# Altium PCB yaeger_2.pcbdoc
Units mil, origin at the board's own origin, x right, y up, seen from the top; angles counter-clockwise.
Board outline 3420.5 x 4365.1 mil, 2 copper layers (Top Layer, Bottom Layer), stack 62.2 mil thick; 11 components, 23 nets, 142 pads, 5 vias.
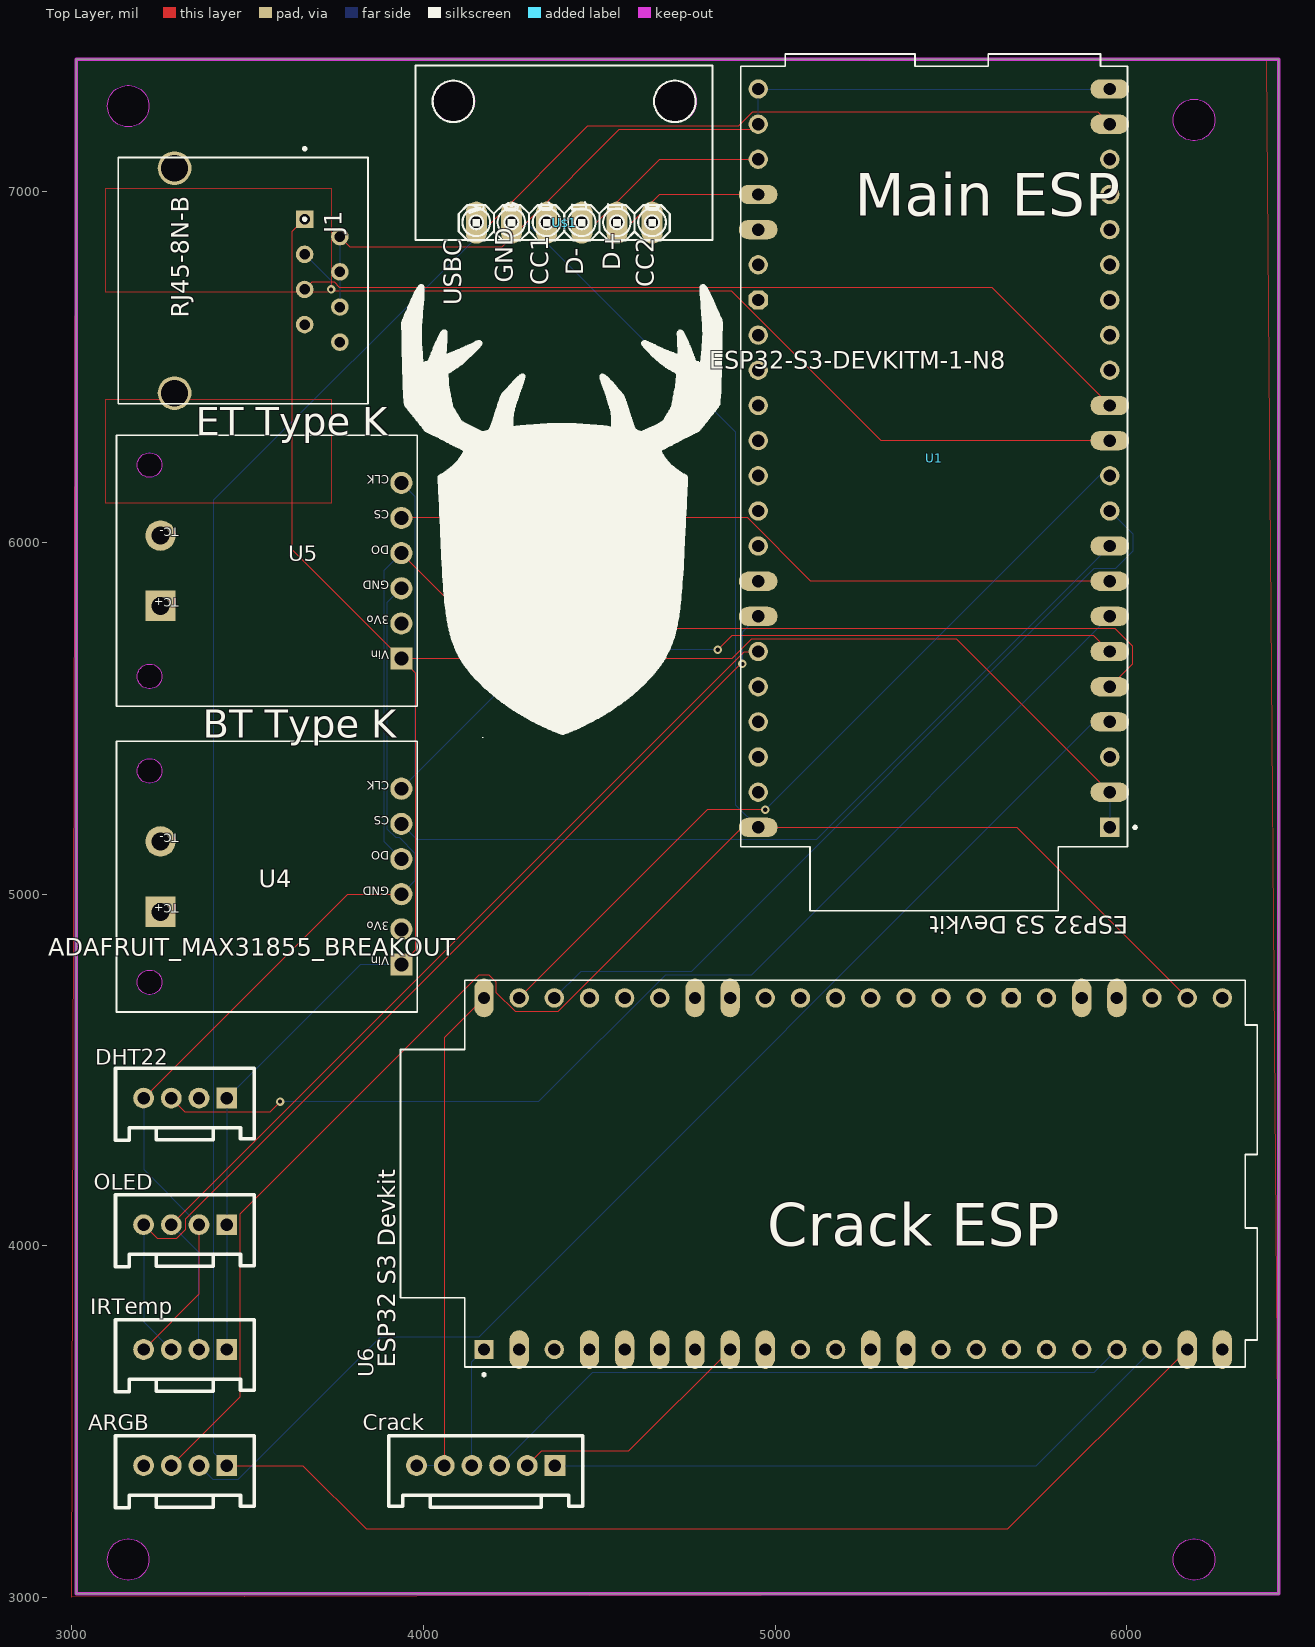
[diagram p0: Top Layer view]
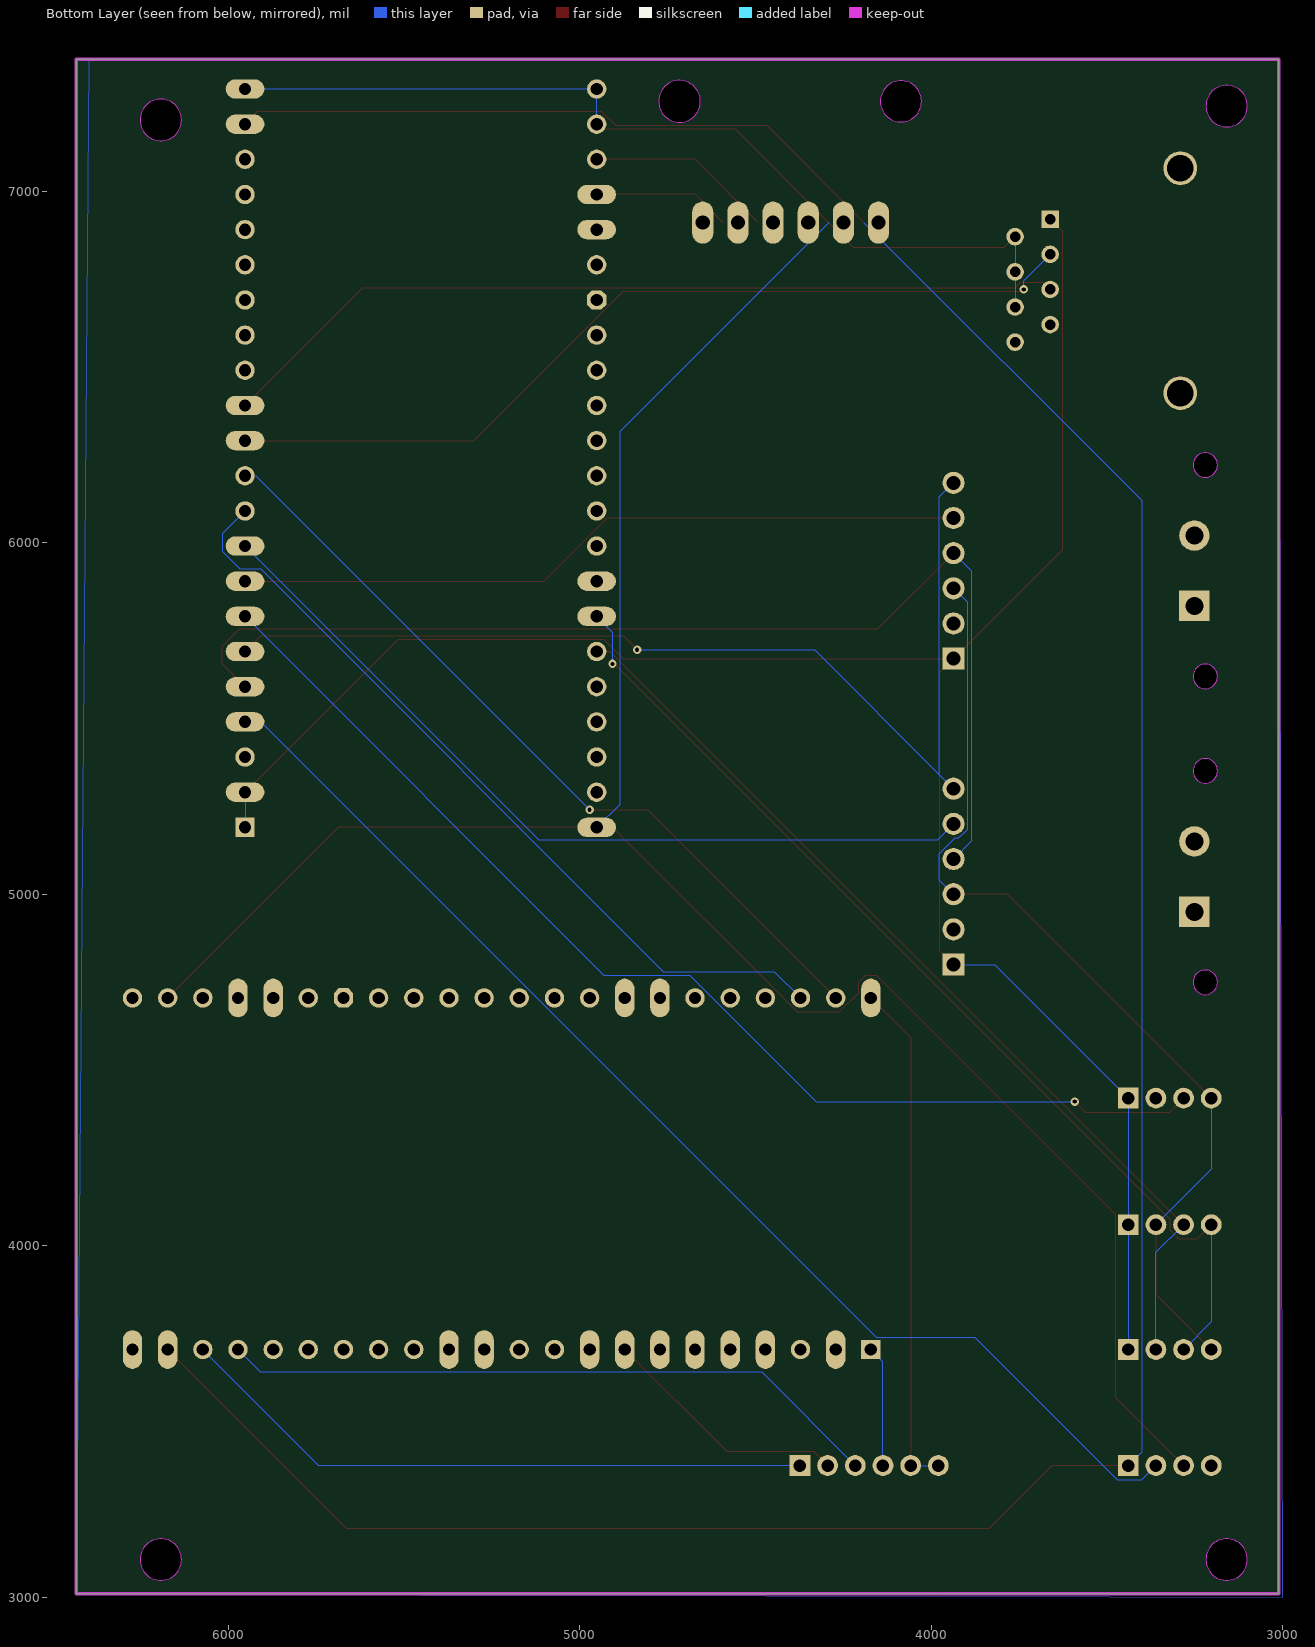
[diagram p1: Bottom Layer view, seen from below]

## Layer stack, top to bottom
Top Solder Mask Layer: solder mask 0.4, Dk 3.3
Top Layer: signal copper 1.4
Dielectric1: surface 59.4, FR4, Dk 4.5
Bottom Layer: signal copper 1.4
Bottom Solder Mask Layer: solder mask 0.4, Dk 3.3

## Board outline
3011.8,7375.1 3011.8,3010 6432.3,3010 6432.3,7375.1
cut-out: 4145.1,7255 4144.7,7248.2 4143.5,7241.5 4141.5,7234.9 4138.8,7228.7 4135.4,7222.8 4131.3,7217.3 4126.7,7212.3 4121.4,7208 4115.7,7204.2 4109.6,7201.1 4103.2,7198.8 4096.6,7197.2 4089.8,7196.4 4083,7196.4 4076.2,7197.2 4069.6,7198.8 4063.2,7201.1 4057.1,7204.2 4051.4,7208 4046.1,7212.3 4041.5,7217.3 4037.4,7222.8 4034,7228.7 4031.3,7234.9 4029.3,7241.5 4028.1,7248.2 4027.7,7255 4028.1,7261.8 4029.3,7268.5 4031.3,7275.1 4034,7281.3 4037.4,7287.3 4041.5,7292.7 4046.1,7297.7 4051.4,7302.1 4057.1,7305.8 4063.2,7308.9 4069.6,7311.2 4076.2,7312.8 4083,7313.6 4089.8,7313.6 4096.6,7312.8 4103.2,7311.2 4109.6,7308.9 4115.7,7305.8 4121.4,7302.1 4126.7,7297.7 4131.3,7292.7 4135.4,7287.3 4138.8,7281.3 4141.5,7275.1 4143.5,7268.5 4144.7,7261.8
cut-out: 4775.9,7255 4775.5,7248.2 4774.4,7241.5 4772.5,7235 4769.8,7228.7 4766.5,7222.8 4762.5,7217.3 4757.9,7212.3 4752.7,7207.8 4747.1,7204 4741.1,7200.8 4734.7,7198.3 4728.2,7196.6 4721.4,7195.6 4714.6,7195.4 4707.8,7196 4701.2,7197.4 4694.7,7199.5 4688.5,7202.3 4682.7,7205.8 4677.3,7210 4672.4,7214.7 4668.1,7220 4664.4,7225.7 4661.4,7231.8 4659.1,7238.2 4657.6,7244.9 4656.8,7251.6 4656.8,7258.4 4657.6,7265.2 4659.1,7271.8 4661.4,7278.2 4664.4,7284.3 4668.1,7290 4672.4,7295.3 4677.3,7300.1 4682.7,7304.2 4688.5,7307.7 4694.7,7310.6 4701.2,7312.7 4707.8,7314 4714.6,7314.6 4721.4,7314.4 4728.2,7313.4 4734.7,7311.7 4741.1,7309.2 4747.1,7306.1 4752.7,7302.2 4757.9,7297.8 4762.5,7292.7 4766.5,7287.2 4769.8,7281.3 4772.5,7275 4774.4,7268.5 4775.5,7261.8
cut-out: 3219,7241.5 3218.6,7234.7 3217.4,7227.9 3215.4,7221.3 3212.7,7215 3209.3,7209.1 3205.2,7203.6 3200.5,7198.6 3195.2,7194.1 3189.5,7190.4 3183.3,7187.3 3176.9,7184.9 3170.2,7183.4 3163.4,7182.6 3156.5,7182.6 3149.7,7183.4 3143,7184.9 3136.6,7187.3 3130.4,7190.4 3124.7,7194.1 3119.4,7198.6 3114.7,7203.6 3110.6,7209.1 3107.2,7215 3104.4,7221.3 3102.5,7227.9 3101.3,7234.7 3100.9,7241.5 3101.3,7248.4 3102.5,7255.1 3104.4,7261.7 3107.2,7268 3110.6,7274 3114.7,7279.5 3119.4,7284.5 3124.7,7288.9 3130.4,7292.7 3136.6,7295.7 3143,7298.1 3149.7,7299.7 3156.5,7300.5 3163.4,7300.5 3170.2,7299.7 3176.9,7298.1 3183.3,7295.7 3189.5,7292.7 3195.2,7288.9 3200.5,7284.5 3205.2,7279.5 3209.3,7274 3212.7,7268 3215.4,7261.7 3217.4,7255.1 3218.6,7248.4
cut-out: 6250.5,7202.1 6250.1,7195.3 6248.9,7188.5 6246.9,7181.9 6244.2,7175.6 6240.8,7169.7 6236.7,7164.2 6232,7159.2 6226.7,7154.8 6221,7151 6214.8,7147.9 6208.4,7145.6 6201.7,7144 6194.9,7143.2 6188,7143.2 6181.2,7144 6174.5,7145.6 6168,7147.9 6161.9,7151 6156.2,7154.8 6150.9,7159.2 6146.2,7164.2 6142.1,7169.7 6138.7,7175.6 6135.9,7181.9 6134,7188.5 6132.8,7195.3 6132.4,7202.1 6132.8,7209 6134,7215.8 6135.9,7222.3 6138.7,7228.6 6142.1,7234.6 6146.2,7240.1 6150.9,7245.1 6156.2,7249.5 6161.9,7253.3 6168,7256.4 6174.5,7258.7 6181.2,7260.3 6188,7261.1 6194.9,7261.1 6201.7,7260.3 6208.4,7258.7 6214.8,7256.4 6221,7253.3 6226.7,7249.5 6232,7245.1 6236.7,7240.1 6240.8,7234.6 6244.2,7228.6 6246.9,7222.3 6248.9,7215.8 6250.1,7209
cut-out: 6250.5,3107.7 6250.1,3100.8 6248.9,3094 6246.9,3087.5 6244.2,3081.1 6240.8,3075.2 6236.7,3069.7 6232,3064.7 6226.7,3060.3 6221,3056.5 6214.8,3053.4 6208.4,3051.1 6201.7,3049.5 6194.9,3048.7 6188,3048.7 6181.2,3049.5 6174.5,3051.1 6168,3053.4 6161.9,3056.5 6156.2,3060.3 6150.9,3064.7 6146.2,3069.7 6142.1,3075.2 6138.7,3081.1 6135.9,3087.5 6134,3094 6132.8,3100.8 6132.4,3107.7 6132.8,3114.5 6134,3121.3 6135.9,3127.9 6138.7,3134.2 6142.1,3140.1 6146.2,3145.6 6150.9,3150.6 6156.2,3155 6161.9,3158.8 6168,3161.9 6174.5,3164.2 6181.2,3165.8 6188,3166.6 6194.9,3166.6 6201.7,3165.8 6208.4,3164.2 6214.8,3161.9 6221,3158.8 6226.7,3155 6232,3150.6 6236.7,3145.6 6240.8,3140.1 6244.2,3134.2 6246.9,3127.9 6248.9,3121.3 6250.1,3114.5
cut-out: 3219,3107.7 3218.6,3100.8 3217.4,3094 3215.4,3087.5 3212.7,3081.1 3209.3,3075.2 3205.2,3069.7 3200.5,3064.7 3195.2,3060.3 3189.5,3056.5 3183.3,3053.4 3176.9,3051.1 3170.2,3049.5 3163.4,3048.7 3156.5,3048.7 3149.7,3049.5 3143,3051.1 3136.6,3053.4 3130.4,3056.5 3124.7,3060.3 3119.4,3064.7 3114.7,3069.7 3110.6,3075.2 3107.2,3081.1 3104.4,3087.5 3102.5,3094 3101.3,3100.8 3100.9,3107.7 3101.3,3114.5 3102.5,3121.3 3104.4,3127.9 3107.2,3134.2 3110.6,3140.1 3114.7,3145.6 3119.4,3150.6 3124.7,3155 3130.4,3158.8 3136.6,3161.9 3143,3164.2 3149.7,3165.8 3156.5,3166.6 3163.4,3166.6 3170.2,3165.8 3176.9,3164.2 3183.3,3161.9 3189.5,3158.8 3195.2,3155 3200.5,3150.6 3205.2,3145.6 3209.3,3140.1 3212.7,3134.2 3215.4,3127.9 3217.4,3121.3 3218.6,3114.5

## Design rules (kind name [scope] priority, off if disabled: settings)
BoardOutlineClearance safeClearance [All] p0: genericclearance=10 ignorepadtopadclearanceinfootprint=FALSE except(0: Arc-SplitContinuation Track-SplitContinuation SMDPad-SplitContinuation THPad-SplitContinuation Via-SplitContinuation Fill-SplitContinuation Poly-SplitContinuation Region-SplitContinuation Text-SplitContinuation)
BoardOutlineClearance Plane_innerPlane [All] p0: genericclearance=10 ignorepadtopadclearanceinfootprint=FALSE except(0: Arc-SplitContinuation Track-SplitContinuation SMDPad-SplitContinuation THPad-SplitContinuation Via-SplitContinuation Fill-SplitContinuation Poly-SplitContinuation Region-SplitContinuation Text-SplitContinuation)
BoardOutlineClearance Copper_CopperRegion [All] p0: genericclearance=10 ignorepadtopadclearanceinfootprint=FALSE except(0: Arc-SplitContinuation Track-SplitContinuation SMDPad-SplitContinuation THPad-SplitContinuation Via-SplitContinuation Fill-SplitContinuation Poly-SplitContinuation Region-SplitContinuation Text-SplitContinuation)
BoardOutlineClearance Copper_CopperRegion1 [All] p0: genericclearance=10 ignorepadtopadclearanceinfootprint=FALSE except(0: Arc-SplitContinuation Track-SplitContinuation SMDPad-SplitContinuation THPad-SplitContinuation Via-SplitContinuation Fill-SplitContinuation Poly-SplitContinuation Region-SplitContinuation Text-SplitContinuation)
BoardOutlineClearance otherClearance [All] p0: genericclearance=10 ignorepadtopadclearanceinfootprint=FALSE except(0: Arc-SplitContinuation Track-SplitContinuation SMDPad-SplitContinuation THPad-SplitContinuation Via-SplitContinuation Fill-SplitContinuation Poly-SplitContinuation Region-SplitContinuation Text-SplitContinuation)
Clearance safeClearance [All] p1: gap=7 ignorepadtopadclearanceinfootprint=FALSE
Clearance Plane_innerPlane [All] p1: gap=7 ignorepadtopadclearanceinfootprint=FALSE
Clearance Copper_CopperRegion [All] p1: gap=7 ignorepadtopadclearanceinfootprint=FALSE
Clearance Copper_CopperRegion1 [All] p1: gap=7 ignorepadtopadclearanceinfootprint=FALSE
Clearance otherClearance [All] p1: gap=7 ignorepadtopadclearanceinfootprint=FALSE
DiffPairsRouting differentialPair [All] p1: maxuncoupledlength=10 minlimit=6 maxlimit=Infinity mostfreqgap=6 toplayer_minwidth=5 toplayer_prefwidth=10 toplayer_maxwidth=100 bottomlayer_minwidth=5 bottomlayer_prefwidth=10 bottomlayer_maxwidth=100
PasteMaskExpansion Common [All] p1: expansion=0
PlaneConnect innerPlane [All] p1: planeconnectstyle=Relief reliefexpansion=20 reliefentries=4 reliefconductorwidth=10 reliefairgap=10
PolygonConnect CopperRegion [All] p1: connectstyle=Relief reliefentries=4 reliefconductorwidth=0 polygonreliefangle="90 Angle" airgapwidth=1
PolygonConnect CopperRegion1 [All] p1: connectstyle=Relief reliefentries=4 reliefconductorwidth=0 polygonreliefangle="90 Angle" airgapwidth=1
RoutingVias viaSize [All] p1: viastyle="Through Hole" holewidth=13.7796 minholewidth=13.7796 maxholewidth=78.7402 width=13.7796 minwidth=13.7796 maxwidth=78.7402
RoutingVias default [All] p1: viastyle="Through Hole" holewidth=12.0078 minholewidth=11.811 maxholewidth=248.0316 width=12.0078 minwidth=11.811 maxwidth=248.0316
SolderMaskExpansion Common [All] p1: useseparateexpansions=TRUE expansion=0 expansionbottom=0
Width trackWidth [All] p1: maxlimit=100 minlimit=8 preferedwidth=8
Width default [All] p1: maxlimit=100 minlimit=0 preferedwidth=0

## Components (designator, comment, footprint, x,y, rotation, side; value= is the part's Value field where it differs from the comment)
ARGB "HC-HY-4A" CONN-TH_4P-P2.00_HCTL_HC-HY-4A 3321.8,3375 r0 top
Crack "XD-HY-6A" CONN-TH_6P-P2.00_HCTL_HC-HY-6A 4176.8,3375 r180 top
DHT22 "HC-HY-4A" CONN-TH_4P-P2.00_HCTL_HC-HY-4A 3321.8,4420 r0 top
IRTemp "HC-HY-4A" CONN-TH_4P-P2.00_HCTL_HC-HY-4A 3321.8,3705 r0 top
J1 "RJ45-8N-B" TE_RJ45-8N-B 3411.8,6745 r270 top
OLED "HC-HY-4A" CONN-TH_4P-P2.00_HCTL_HC-HY-4A 3321.8,4060 r0 top
U1 "ESP32-S3-DEVKITM-1-N8" MODULE_ESP32-S3-DEVKITM-1-N8 5501.8,6370 r180 top
U4 "ADAFRUIT_MAX31855_BREAKOUT" ADAFRUIT_MAX31855_BREAKOUT 3586.8,5050 r180 top
U5 "ADAFRUIT_MAX31855_BREAKOUT" ADAFRUIT_MAX31855_BREAKOUT 3586.8,5920 r180 top
U6 "ESP32-S3-DEVKITM-1-N8" MODULE_ESP32-S3-DEVKITM-1-N8 5351.8,4155 r90 top
U$1 "USBC" 1X06 4400.1,6910 r0 top

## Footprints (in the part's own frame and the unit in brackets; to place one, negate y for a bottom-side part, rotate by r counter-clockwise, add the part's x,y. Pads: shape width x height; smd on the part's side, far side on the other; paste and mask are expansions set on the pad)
1X06 [mil]
  oval 60x120 hole 40 paste+0 mask+4: 1(-250,0) 2(-150,0) 3(-50,0) 4(50,0) 5(150,0) 6(250,0)
  silkscreen extent -423,-50 422,447
ADAFRUIT_MAX31855_BREAKOUT [mil]
  rect 63x63 hole 39.4 paste+0 mask+4: 1(-350,250)
  round 63 hole 39.4 paste+0 mask+4: 2(-350,150) 3(-350,50) 4(-350,-50) 5(-350,-150) 6(-350,-250)
  rect 86.6x86.6 hole 51.2 paste+0 mask+4: 7(335,100)
  round 86.6 hole 51.2 paste+0 mask+4: 8(335,-100)
  Board Outline Layer lines w0.1: 401.1,300.6 400.7,295.4 399.6,290.3 397.6,285.4 395,280.9 391.8,276.8 387.9,273.3 383.6,270.3 378.9,268 373.9,266.5 368.7,265.7 363.5,265.7 358.3,266.5 353.3,268 348.6,270.3 344.3,273.3 340.5,276.8 337.2,280.9 334.6,285.4 332.7,290.3 331.5,295.4 331.1,300.6 331.5,305.8 332.7,310.9 334.6,315.8 337.2,320.3 340.5,324.4 344.3,328 348.6,330.9 353.3,333.2 358.3,334.7 363.5,335.5 368.7,335.5 373.9,334.7 378.9,333.2 383.6,330.9 387.9,328 391.8,324.4 395,320.3 397.6,315.8 399.6,310.9 400.7,305.8 401.1,300.6 ; 401.1,-300.6 400.7,-305.9 399.6,-311 397.6,-315.8 395,-320.4 391.8,-324.5 387.9,-328 383.6,-331 378.9,-333.2 373.9,-334.8 368.7,-335.5 363.5,-335.5 358.3,-334.8 353.3,-333.2 348.6,-331 344.3,-328 340.5,-324.5 337.2,-320.4 334.6,-315.8 332.7,-311 331.5,-305.9 331.1,-300.6 331.5,-295.4 332.7,-290.3 334.6,-285.5 337.2,-280.9 340.5,-276.8 344.3,-273.3 348.6,-270.3 353.3,-268.1 358.3,-266.5 363.5,-265.7 368.7,-265.7 373.9,-266.5 378.9,-268.1 383.6,-270.3 387.9,-273.3 391.8,-276.8 395,-280.9 397.6,-285.5 399.6,-290.3 400.7,-295.4 401.1,-300.6
  Board Outline Layer region: 401.1,300.6 400.7,295.4 399.6,290.3 397.6,285.4 395,280.9 391.8,276.8 387.9,273.3 383.6,270.3 378.9,268 373.9,266.5 368.7,265.7 363.5,265.7 358.3,266.5 353.3,268 348.6,270.3 344.3,273.3 340.5,276.8 337.2,280.9 334.6,285.4 332.7,290.3 331.5,295.4 331.1,300.6 331.5,305.8 332.7,310.9 334.6,315.8 337.2,320.3 340.5,324.4 344.3,328 348.6,330.9 353.3,333.2 358.3,334.7 363.5,335.5 368.7,335.5 373.9,334.7 378.9,333.2 383.6,330.9 387.9,328 391.8,324.4 395,320.3 397.6,315.8 399.6,310.9 400.7,305.8
  Board Outline Layer region: 401.1,300.6 400.7,295.4 399.6,290.3 397.6,285.4 395,280.9 391.8,276.8 387.9,273.3 383.6,270.3 378.9,268 373.9,266.5 368.7,265.7 363.5,265.7 358.3,266.5 353.3,268 348.6,270.3 344.3,273.3 340.5,276.8 337.2,280.9 334.6,285.4 332.7,290.3 331.5,295.4 331.1,300.6 331.5,305.8 332.7,310.9 334.6,315.8 337.2,320.3 340.5,324.4 344.3,328 348.6,330.9 353.3,333.2 358.3,334.7 363.5,335.5 368.7,335.5 373.9,334.7 378.9,333.2 383.6,330.9 387.9,328 391.8,324.4 395,320.3 397.6,315.8 399.6,310.9 400.7,305.8
  Board Outline Layer region: 401.1,-300.6 400.7,-305.9 399.6,-311 397.6,-315.8 395,-320.4 391.8,-324.5 387.9,-328 383.6,-331 378.9,-333.2 373.9,-334.8 368.7,-335.5 363.5,-335.5 358.3,-334.8 353.3,-333.2 348.6,-331 344.3,-328 340.5,-324.5 337.2,-320.4 334.6,-315.8 332.7,-311 331.5,-305.9 331.1,-300.6 331.5,-295.4 332.7,-290.3 334.6,-285.5 337.2,-280.9 340.5,-276.8 344.3,-273.3 348.6,-270.3 353.3,-268.1 358.3,-266.5 363.5,-265.7 368.7,-265.7 373.9,-266.5 378.9,-268.1 383.6,-270.3 387.9,-273.3 391.8,-276.8 395,-280.9 397.6,-285.5 399.6,-290.3 400.7,-295.4
  Board Outline Layer region: 401.1,-300.6 400.7,-305.9 399.6,-311 397.6,-315.8 395,-320.4 391.8,-324.5 387.9,-328 383.6,-331 378.9,-333.2 373.9,-334.8 368.7,-335.5 363.5,-335.5 358.3,-334.8 353.3,-333.2 348.6,-331 344.3,-328 340.5,-324.5 337.2,-320.4 334.6,-315.8 332.7,-311 331.5,-305.9 331.1,-300.6 331.5,-295.4 332.7,-290.3 334.6,-285.5 337.2,-280.9 340.5,-276.8 344.3,-273.3 348.6,-270.3 353.3,-268.1 358.3,-266.5 363.5,-265.7 368.7,-265.7 373.9,-266.5 378.9,-268.1 383.6,-270.3 387.9,-273.3 391.8,-276.8 395,-280.9 397.6,-285.5 399.6,-290.3 400.7,-295.4
  Multi-Layer board cut-out: 401.1,300.6 400.7,295.4 399.6,290.3 397.6,285.4 395,280.9 391.8,276.8 387.9,273.3 383.6,270.3 378.9,268 373.9,266.5 368.7,265.7 363.5,265.7 358.3,266.5 353.3,268 348.6,270.3 344.3,273.3 340.5,276.8 337.2,280.9 334.6,285.4 332.7,290.3 331.5,295.4 331.1,300.6 331.5,305.8 332.7,310.9 334.6,315.8 337.2,320.3 340.5,324.4 344.3,328 348.6,330.9 353.3,333.2 358.3,334.7 363.5,335.5 368.7,335.5 373.9,334.7 378.9,333.2 383.6,330.9 387.9,328 391.8,324.4 395,320.3 397.6,315.8 399.6,310.9 400.7,305.8
  Multi-Layer board cut-out: 401.1,-300.6 400.7,-305.9 399.6,-311 397.6,-315.8 395,-320.4 391.8,-324.5 387.9,-328 383.6,-331 378.9,-333.2 373.9,-334.8 368.7,-335.5 363.5,-335.5 358.3,-334.8 353.3,-333.2 348.6,-331 344.3,-328 340.5,-324.5 337.2,-320.4 334.6,-315.8 332.7,-311 331.5,-305.9 331.1,-300.6 331.5,-295.4 332.7,-290.3 334.6,-285.5 337.2,-280.9 340.5,-276.8 344.3,-273.3 348.6,-270.3 353.3,-268.1 358.3,-266.5 363.5,-265.7 368.7,-265.7 373.9,-266.5 378.9,-268.1 383.6,-270.3 387.9,-273.3 391.8,-276.8 395,-280.9 397.6,-285.5 399.6,-290.3 400.7,-295.4
  silkscreen extent -395,-385 460,385
CONN-TH_4P-P2.00_HCTL_HC-HY-4A [mil]
  rect 59.1x59.1 hole 35.4 paste+0 mask+2: 1(118.1,0)
  round 59.1 hole 35.4 paste+0 mask+2: 2(39.4,0) 3(-39.3,0) 4(-118.1,0)
  silkscreen extent -198,-120 197,85
CONN-TH_6P-P2.00_HCTL_HC-HY-6A [mil]
  rect 59.1x59.1 hole 35.4 paste+0 mask+2: 1(-196.9,0)
  round 59.1 hole 35.4 paste+0 mask+2: 2(-118.1,0) 3(-39.4,0) 4(39.3,0) 5(118.1,0) 6(196.8,0)
  silkscreen extent -276,-85 276,118
MODULE_ESP32-S3-DEVKITM-1-N8 [mil]
  rect 55x55 hole 35 paste+0 mask+4: J11(-450,1179.9)
  oval 110x55 hole 35 paste+0 mask+4: J12(-450,1079.9) J14(-450,879.9) J15(-450,779.9) J16(-450,679.9) J17(-450,579.9) J18(-450,479.9) J19(-450,379.9) J31(550,1179.9) J37(550,579.9) J38(550,479.9) J112(-450,79.9) J113(-450,-20.1) J121(-450,-820.1) J122(-450,-920.1) J318(550,-520.1) J319(550,-620.1)
  round 55 hole 35 paste+0 mask+4: J13(-450,979.9) J32(550,1079.9) J33(550,979.9) J34(550,879.9) J35(550,779.9) J36(550,679.9) J39(550,379.9) J110(-450,279.9) J111(-450,179.9) J114(-450,-120.1) J115(-450,-220.1) J116(-450,-320.1) J117(-450,-420.1) J118(-450,-520.1) J119(-450,-620.1) J120(-450,-720.1) J310(550,279.9) J311(550,179.9) J312(550,79.9) J313(550,-20.1) J314(550,-120.1) J315(550,-220.1) J317(550,-420.1) J320(550,-720.1) J321(550,-820.1) J322(550,-920.1)
  oct 55x55 hole 35 paste+0 mask+4: J316(550,-320.1)
  silkscreen extent -526,-1019 600,1417
TE_RJ45-8N-B [mil]
  rect 49.9x49.9 hole 29.9 paste+0 mask+4: 1(-175,250)
  round 49.9 hole 29.9 paste+0 mask+4: 2(-125,350) 3(-75,250) 4(-25,350) 5(25,250) 6(75,350) 7(125,250) 8(175,350)
  round 96 hole 76 paste+0 mask+4: 9(-319.9,-120) 10(319.9,-120)
  silkscreen extent -379,-280 350,430

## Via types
v1: diameter 24, hole 12, Top Layer to Bottom Layer, 5 vias

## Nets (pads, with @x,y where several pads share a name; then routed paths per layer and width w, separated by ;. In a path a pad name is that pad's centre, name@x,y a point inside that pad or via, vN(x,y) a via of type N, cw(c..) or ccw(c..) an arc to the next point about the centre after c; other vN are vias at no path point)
$1N21: U1.J16 U4.6 U5.6 | length 3060.4
  Top Layer w0.1: v1(4836.8,5695.1) 4876.8,5735.1 5906.8,5735.1 U1.J16
  Bottom Layer w0.1: U4.6 3976.8,5340 ; U5.6 3976.8,6130 3976.8,5340 ; v1(4836.8,5695.1) 4331.9,5695.1 3976.8,5340
$1N209: U1.J111 U6.J32 | length 2295
  Top Layer w0.1: U6.J32 4807,5240.1 v1(4971.8,5240.1)
  Bottom Layer w0.1: v1(4971.8,5240.1) 5921.8,6190.1 U1.J111
$1N210: U1.J110 U6.J33 | length 2312.9
  Bottom Layer w0.1: U6.J33 4447,4780.1 4761.8,4780.1 5906.8,5925.1 5966.8,5925.1 6016.8,5975.1 6016.8,6025.1 U1.J110
$1N212: DHT22.3 U1.J17 | length 3269.9
  Top Layer w0.1: DHT22.3 3322.4,4380.1 3561.8,4380.1 v1(3591.8,4410.1)
  Bottom Layer w0.1: v1(3591.8,4410.1) 4326.8,4410.1 4686.8,4770.1 4931.8,4770.1 U1.J17
$1N218: Crack.1 U6.J120 | length 1834.9
  Bottom Layer w0.1: Crack.1 5741.9,3375 U6.J120
$1N220: Crack.3 U6.J119 | length 1892.4
  Bottom Layer w0.1: Crack.3 4481.2,3640 5906.9,3640 U6.J119
$1N221: Crack.2 U6.J18 | length 713.7
  Top Layer w0.1: Crack.2 4334.9,3415 4581.9,3415 U6.J18
$1N222: Crack.4 U6.J11 | length 344.2
  Bottom Layer w0.1: Crack.4 4137.5,3670.6 U6.J11
$1N223: Crack.5 Crack.6 U6.J31 | length 1455.6
  Top Layer w0.1: Crack.5 4058.7,4591.8 U6.J31
  Bottom Layer w0.1: Crack.6 Crack.5
+5V: ARGB.1 U1.J121 U6.J121 U$1.1 | length 8800.9
  Top Layer w0.1: ARGB.1 3656.8,3375 3836.8,3195 5661.9,3195 U6.J121 ; 4191.8,6910 4466.9,7185.1 4896.8,7185.1 4936.8,7225.1 5916.9,7225.1 U1.J121
  Bottom Layer w0.1: ARGB.1 3401.8,3413.1 3401.8,6120 4191.8,6910
AGND: DHT22.4 IRTemp.4 OLED.2 U4.3 U5.3 | length 2761
  Top Layer w0.1: IRTemp.4 3361.2,3862.5 OLED.2 ; DHT22.4 3783.7,5000 U4.3
  Bottom Layer w0.1: DHT22.4 3203.7,4217.5 OLED.2 ; U4.3 3976.8,5040 3976.8,5115 3931.8,5160 3921.8,5160 3896.8,5185 3896.8,5830 U5.3
CS2: U1.J19 U4.5 | length 2379.5
  Bottom Layer w0.1: U4.5 3981.7,5155.1 5116.8,5155.1 U1.J19
DA: IRTemp.3 OLED.4 U1.J37 | length 2955.7
  Top Layer w0.1: OLED.4 3243.6,4020.1 3296.8,4020.1 3321.8,4045.1 3321.8,4075.1 4901.8,5655.1 v1(4906.8,5655.1)
  Bottom Layer w0.1: OLED.4 3203.7,3783.8 IRTemp.3 ; v1(4906.8,5655.1) 4906.8,5745.1 U1.J37
DO: U1.J15 U4.4 U5.4 | length 3243.2
  Top Layer w0.1: U5.4 4151.8,5755.1 5966.9,5755.1 6016.9,5705.1 6016.9,5655.2 U1.J15
  Bottom Layer w0.1: U4.4 3886.8,5150 3886.8,5920 U5.4
GND: ARGB.3 J1.2 J1.4 J1.6 U1.J31 U1.J122 U1.J321 U1.J322 U6.J122 U6.J321 U$1.2 | length 8892.5
  Top Layer w0.1: ARGB.3 3476.8,3569.3 3476.8,4090.1 4156.8,4770.1 4186.8,4770.1 4206.8,4750.1 4206.8,4720.1 4261.8,4665.1 4381.8,4665.1 4906.8,5190.1 U1.J31 5686.8,5190.1 U6.J321 ; J1.2 3791.9,6840 4221.8,6840 4291.8,6910 4556.9,7175.1 4936.8,7175.1 U1.J321
  Bottom Layer w0.1: J1.6 J1.4 J1.2 ; 4291.8,6910 4886.8,6315 4886.8,5255.1 U1.J31 ; U1.J321 U1.J322 U1.J122
N$1: ARGB.2 U1.J14 | length 3499.8
  Bottom Layer w0.1: ARGB.2 3401.1,3335.1 3471.8,3335.1 3876.8,3740.1 4156.8,3740.1 5906.8,5490.1 U1.J14
N$2: U1.J18 U5.5 | length 2089.5
  Top Layer w0.1: U5.5@3936.9,6070.1 4921.8,6070.1 5101.8,5890.1 U1.J18
N$4: U1.J320 U$1.4 | length 534.6
  Top Layer w0.1: 4491.8,6910 4671.9,7090.1 U1.J320
N$5: J1.3 U1.J112 | length 2524.1
  Top Layer w0.1: v1(3736.8,6720.1) 3741.8,6715.1 4876.8,6715.1 5301.8,6290.1 U1.J112
  Bottom Layer w0.1: J1.3 3736.8,6745.1 v1(3736.8,6720.1)
N$6: J1.5 U1.J113 | length 2443.3
  Top Layer w0.1: J1.5 3681.9,6740.1 3746.8,6740.1 3761.8,6725.1 5616.8,6725.1 U1.J113
N$7: U1.J319 U$1.5 | length 393.2
  Top Layer w0.1: 4591.8,6910 4671.9,6990.1 U1.J319
SC: IRTemp.2 OLED.3 U1.J36 | length 2732.1
  Top Layer w0.1: OLED.3 4912.5,5690.1 U1.J36
  Bottom Layer w0.1: OLED.3 3361.2,3981.3 IRTemp.2
VCC: DHT22.1 IRTemp.1 J1.1 OLED.1 U1.J11 U1.J12 U4.1 U5.1 | length 5983.2
  Top Layer w0.1: J1.1 3626.8,6885 3626.8,5980 U5.1 3976.8,5630 3976.8,4840 U4.1 ; U5.1@3936.9,5670.1 4876.8,5670.1 4931.8,5725.1 5516.8,5725.1 U1.J12
  Bottom Layer w0.1: IRTemp.1 OLED.1 DHT22.1 3819.9,4800 U4.1 ; U1.J11 U1.J12
pads on no net: ARGB.4 DHT22.2 J1.7 J1.8 J1.9 J1.10 U1.J13 U1.J32 U1.J33 U1.J34 U1.J35 U1.J38 U1.J39 U1.J114 U1.J115 U1.J116 U1.J117 U1.J118 U1.J119 U1.J120 U1.J310 U1.J311 U1.J312 U1.J313 U1.J314 U1.J315 U1.J316 U1.J317 U1.J318 U4.2 U4.7 U4.8 U5.2 U5.7 U5.8 U6.J12 U6.J13 U6.J14 U6.J15 U6.J16 U6.J17 U6.J19 U6.J34 U6.J35 U6.J36 U6.J37 U6.J38 U6.J39 U6.J110 U6.J111 U6.J112 U6.J113 U6.J114 U6.J115 U6.J116 U6.J117 U6.J118 U6.J310 U6.J311 U6.J312 U6.J313 U6.J314 U6.J315 U6.J316 U6.J317 U6.J318 U6.J319 U6.J320 U6.J322 U$1.3 U$1.6

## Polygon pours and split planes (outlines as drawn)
GND on Bottom Layer (solid, pour order 6): 3000,3000 3011.8,7375.1 6396.8,7370 6432.3,3010
GND on Top Layer (solid, remove dead copper, pour order 0): 3000,3000 3011.8,7375.1 6396.8,7370 6432.3,3010
no net on Top Layer (solid, remove dead copper, pour order 2): 3094.8,6713 3738.8,6713 3738.8,7007 3094.8,7007
no net on Top Layer (solid, remove dead copper, pour order 4): 3094.8,6113 3738.8,6113 3738.8,6407 3094.8,6407

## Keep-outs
Board Outline Layer:
  region: 4145.1,7255 4144.7,7248.2 4143.5,7241.5 4141.5,7234.9 4138.8,7228.7 4135.4,7222.8 4131.3,7217.3 4126.7,7212.3 4121.4,7208 4115.7,7204.2 4109.6,7201.1 4103.2,7198.8 4096.6,7197.2 4089.8,7196.4 4083,7196.4 4076.2,7197.2 4069.6,7198.8 4063.2,7201.1 4057.1,7204.2 4051.4,7208 4046.1,7212.3 4041.5,7217.3 4037.4,7222.8 4034,7228.7 4031.3,7234.9 4029.3,7241.5 4028.1,7248.2 4027.7,7255 4028.1,7261.8 4029.3,7268.5 4031.3,7275.1 4034,7281.3 4037.4,7287.3 4041.5,7292.7 4046.1,7297.7 4051.4,7302.1 4057.1,7305.8 4063.2,7308.9 4069.6,7311.2 4076.2,7312.8 4083,7313.6 4089.8,7313.6 4096.6,7312.8 4103.2,7311.2 4109.6,7308.9 4115.7,7305.8 4121.4,7302.1 4126.7,7297.7 4131.3,7292.7 4135.4,7287.3 4138.8,7281.3 4141.5,7275.1 4143.5,7268.5 4144.7,7261.8
  region: 4145.1,7255 4144.7,7248.2 4143.5,7241.5 4141.5,7234.9 4138.8,7228.7 4135.4,7222.8 4131.3,7217.3 4126.7,7212.3 4121.4,7208 4115.7,7204.2 4109.6,7201.1 4103.2,7198.8 4096.6,7197.2 4089.8,7196.4 4083,7196.4 4076.2,7197.2 4069.6,7198.8 4063.2,7201.1 4057.1,7204.2 4051.4,7208 4046.1,7212.3 4041.5,7217.3 4037.4,7222.8 4034,7228.7 4031.3,7234.9 4029.3,7241.5 4028.1,7248.2 4027.7,7255 4028.1,7261.8 4029.3,7268.5 4031.3,7275.1 4034,7281.3 4037.4,7287.3 4041.5,7292.7 4046.1,7297.7 4051.4,7302.1 4057.1,7305.8 4063.2,7308.9 4069.6,7311.2 4076.2,7312.8 4083,7313.6 4089.8,7313.6 4096.6,7312.8 4103.2,7311.2 4109.6,7308.9 4115.7,7305.8 4121.4,7302.1 4126.7,7297.7 4131.3,7292.7 4135.4,7287.3 4138.8,7281.3 4141.5,7275.1 4143.5,7268.5 4144.7,7261.8
  region: 4775.9,7255 4775.5,7248.2 4774.4,7241.5 4772.5,7235 4769.8,7228.7 4766.5,7222.8 4762.5,7217.3 4757.9,7212.3 4752.7,7207.8 4747.1,7204 4741.1,7200.8 4734.7,7198.3 4728.2,7196.6 4721.4,7195.6 4714.6,7195.4 4707.8,7196 4701.2,7197.4 4694.7,7199.5 4688.5,7202.3 4682.7,7205.8 4677.3,7210 4672.4,7214.7 4668.1,7220 4664.4,7225.7 4661.4,7231.8 4659.1,7238.2 4657.6,7244.9 4656.8,7251.6 4656.8,7258.4 4657.6,7265.2 4659.1,7271.8 4661.4,7278.2 4664.4,7284.3 4668.1,7290 4672.4,7295.3 4677.3,7300.1 4682.7,7304.2 4688.5,7307.7 4694.7,7310.6 4701.2,7312.7 4707.8,7314 4714.6,7314.6 4721.4,7314.4 4728.2,7313.4 4734.7,7311.7 4741.1,7309.2 4747.1,7306.1 4752.7,7302.2 4757.9,7297.8 4762.5,7292.7 4766.5,7287.2 4769.8,7281.3 4772.5,7275 4774.4,7268.5 4775.5,7261.8
  region: 4775.9,7255 4775.5,7248.2 4774.4,7241.5 4772.5,7235 4769.8,7228.7 4766.5,7222.8 4762.5,7217.3 4757.9,7212.3 4752.7,7207.8 4747.1,7204 4741.1,7200.8 4734.7,7198.3 4728.2,7196.6 4721.4,7195.6 4714.6,7195.4 4707.8,7196 4701.2,7197.4 4694.7,7199.5 4688.5,7202.3 4682.7,7205.8 4677.3,7210 4672.4,7214.7 4668.1,7220 4664.4,7225.7 4661.4,7231.8 4659.1,7238.2 4657.6,7244.9 4656.8,7251.6 4656.8,7258.4 4657.6,7265.2 4659.1,7271.8 4661.4,7278.2 4664.4,7284.3 4668.1,7290 4672.4,7295.3 4677.3,7300.1 4682.7,7304.2 4688.5,7307.7 4694.7,7310.6 4701.2,7312.7 4707.8,7314 4714.6,7314.6 4721.4,7314.4 4728.2,7313.4 4734.7,7311.7 4741.1,7309.2 4747.1,7306.1 4752.7,7302.2 4757.9,7297.8 4762.5,7292.7 4766.5,7287.2 4769.8,7281.3 4772.5,7275 4774.4,7268.5 4775.5,7261.8
  region: 3219,7241.5 3218.6,7234.7 3217.4,7227.9 3215.4,7221.3 3212.7,7215 3209.3,7209.1 3205.2,7203.6 3200.5,7198.6 3195.2,7194.1 3189.5,7190.4 3183.3,7187.3 3176.9,7184.9 3170.2,7183.4 3163.4,7182.6 3156.5,7182.6 3149.7,7183.4 3143,7184.9 3136.6,7187.3 3130.4,7190.4 3124.7,7194.1 3119.4,7198.6 3114.7,7203.6 3110.6,7209.1 3107.2,7215 3104.4,7221.3 3102.5,7227.9 3101.3,7234.7 3100.9,7241.5 3101.3,7248.4 3102.5,7255.1 3104.4,7261.7 3107.2,7268 3110.6,7274 3114.7,7279.5 3119.4,7284.5 3124.7,7288.9 3130.4,7292.7 3136.6,7295.7 3143,7298.1 3149.7,7299.7 3156.5,7300.5 3163.4,7300.5 3170.2,7299.7 3176.9,7298.1 3183.3,7295.7 3189.5,7292.7 3195.2,7288.9 3200.5,7284.5 3205.2,7279.5 3209.3,7274 3212.7,7268 3215.4,7261.7 3217.4,7255.1 3218.6,7248.4
  region: 3219,7241.5 3218.6,7234.7 3217.4,7227.9 3215.4,7221.3 3212.7,7215 3209.3,7209.1 3205.2,7203.6 3200.5,7198.6 3195.2,7194.1 3189.5,7190.4 3183.3,7187.3 3176.9,7184.9 3170.2,7183.4 3163.4,7182.6 3156.5,7182.6 3149.7,7183.4 3143,7184.9 3136.6,7187.3 3130.4,7190.4 3124.7,7194.1 3119.4,7198.6 3114.7,7203.6 3110.6,7209.1 3107.2,7215 3104.4,7221.3 3102.5,7227.9 3101.3,7234.7 3100.9,7241.5 3101.3,7248.4 3102.5,7255.1 3104.4,7261.7 3107.2,7268 3110.6,7274 3114.7,7279.5 3119.4,7284.5 3124.7,7288.9 3130.4,7292.7 3136.6,7295.7 3143,7298.1 3149.7,7299.7 3156.5,7300.5 3163.4,7300.5 3170.2,7299.7 3176.9,7298.1 3183.3,7295.7 3189.5,7292.7 3195.2,7288.9 3200.5,7284.5 3205.2,7279.5 3209.3,7274 3212.7,7268 3215.4,7261.7 3217.4,7255.1 3218.6,7248.4
  region: 6250.5,7202.1 6250.1,7195.3 6248.9,7188.5 6246.9,7181.9 6244.2,7175.6 6240.8,7169.7 6236.7,7164.2 6232,7159.2 6226.7,7154.8 6221,7151 6214.8,7147.9 6208.4,7145.6 6201.7,7144 6194.9,7143.2 6188,7143.2 6181.2,7144 6174.5,7145.6 6168,7147.9 6161.9,7151 6156.2,7154.8 6150.9,7159.2 6146.2,7164.2 6142.1,7169.7 6138.7,7175.6 6135.9,7181.9 6134,7188.5 6132.8,7195.3 6132.4,7202.1 6132.8,7209 6134,7215.8 6135.9,7222.3 6138.7,7228.6 6142.1,7234.6 6146.2,7240.1 6150.9,7245.1 6156.2,7249.5 6161.9,7253.3 6168,7256.4 6174.5,7258.7 6181.2,7260.3 6188,7261.1 6194.9,7261.1 6201.7,7260.3 6208.4,7258.7 6214.8,7256.4 6221,7253.3 6226.7,7249.5 6232,7245.1 6236.7,7240.1 6240.8,7234.6 6244.2,7228.6 6246.9,7222.3 6248.9,7215.8 6250.1,7209
  region: 6250.5,7202.1 6250.1,7195.3 6248.9,7188.5 6246.9,7181.9 6244.2,7175.6 6240.8,7169.7 6236.7,7164.2 6232,7159.2 6226.7,7154.8 6221,7151 6214.8,7147.9 6208.4,7145.6 6201.7,7144 6194.9,7143.2 6188,7143.2 6181.2,7144 6174.5,7145.6 6168,7147.9 6161.9,7151 6156.2,7154.8 6150.9,7159.2 6146.2,7164.2 6142.1,7169.7 6138.7,7175.6 6135.9,7181.9 6134,7188.5 6132.8,7195.3 6132.4,7202.1 6132.8,7209 6134,7215.8 6135.9,7222.3 6138.7,7228.6 6142.1,7234.6 6146.2,7240.1 6150.9,7245.1 6156.2,7249.5 6161.9,7253.3 6168,7256.4 6174.5,7258.7 6181.2,7260.3 6188,7261.1 6194.9,7261.1 6201.7,7260.3 6208.4,7258.7 6214.8,7256.4 6221,7253.3 6226.7,7249.5 6232,7245.1 6236.7,7240.1 6240.8,7234.6 6244.2,7228.6 6246.9,7222.3 6248.9,7215.8 6250.1,7209
  region: 6250.5,3107.7 6250.1,3100.8 6248.9,3094 6246.9,3087.5 6244.2,3081.1 6240.8,3075.2 6236.7,3069.7 6232,3064.7 6226.7,3060.3 6221,3056.5 6214.8,3053.4 6208.4,3051.1 6201.7,3049.5 6194.9,3048.7 6188,3048.7 6181.2,3049.5 6174.5,3051.1 6168,3053.4 6161.9,3056.5 6156.2,3060.3 6150.9,3064.7 6146.2,3069.7 6142.1,3075.2 6138.7,3081.1 6135.9,3087.5 6134,3094 6132.8,3100.8 6132.4,3107.7 6132.8,3114.5 6134,3121.3 6135.9,3127.9 6138.7,3134.2 6142.1,3140.1 6146.2,3145.6 6150.9,3150.6 6156.2,3155 6161.9,3158.8 6168,3161.9 6174.5,3164.2 6181.2,3165.8 6188,3166.6 6194.9,3166.6 6201.7,3165.8 6208.4,3164.2 6214.8,3161.9 6221,3158.8 6226.7,3155 6232,3150.6 6236.7,3145.6 6240.8,3140.1 6244.2,3134.2 6246.9,3127.9 6248.9,3121.3 6250.1,3114.5
  region: 6250.5,3107.7 6250.1,3100.8 6248.9,3094 6246.9,3087.5 6244.2,3081.1 6240.8,3075.2 6236.7,3069.7 6232,3064.7 6226.7,3060.3 6221,3056.5 6214.8,3053.4 6208.4,3051.1 6201.7,3049.5 6194.9,3048.7 6188,3048.7 6181.2,3049.5 6174.5,3051.1 6168,3053.4 6161.9,3056.5 6156.2,3060.3 6150.9,3064.7 6146.2,3069.7 6142.1,3075.2 6138.7,3081.1 6135.9,3087.5 6134,3094 6132.8,3100.8 6132.4,3107.7 6132.8,3114.5 6134,3121.3 6135.9,3127.9 6138.7,3134.2 6142.1,3140.1 6146.2,3145.6 6150.9,3150.6 6156.2,3155 6161.9,3158.8 6168,3161.9 6174.5,3164.2 6181.2,3165.8 6188,3166.6 6194.9,3166.6 6201.7,3165.8 6208.4,3164.2 6214.8,3161.9 6221,3158.8 6226.7,3155 6232,3150.6 6236.7,3145.6 6240.8,3140.1 6244.2,3134.2 6246.9,3127.9 6248.9,3121.3 6250.1,3114.5
  region: 3219,3107.7 3218.6,3100.8 3217.4,3094 3215.4,3087.5 3212.7,3081.1 3209.3,3075.2 3205.2,3069.7 3200.5,3064.7 3195.2,3060.3 3189.5,3056.5 3183.3,3053.4 3176.9,3051.1 3170.2,3049.5 3163.4,3048.7 3156.5,3048.7 3149.7,3049.5 3143,3051.1 3136.6,3053.4 3130.4,3056.5 3124.7,3060.3 3119.4,3064.7 3114.7,3069.7 3110.6,3075.2 3107.2,3081.1 3104.4,3087.5 3102.5,3094 3101.3,3100.8 3100.9,3107.7 3101.3,3114.5 3102.5,3121.3 3104.4,3127.9 3107.2,3134.2 3110.6,3140.1 3114.7,3145.6 3119.4,3150.6 3124.7,3155 3130.4,3158.8 3136.6,3161.9 3143,3164.2 3149.7,3165.8 3156.5,3166.6 3163.4,3166.6 3170.2,3165.8 3176.9,3164.2 3183.3,3161.9 3189.5,3158.8 3195.2,3155 3200.5,3150.6 3205.2,3145.6 3209.3,3140.1 3212.7,3134.2 3215.4,3127.9 3217.4,3121.3 3218.6,3114.5
  region: 3219,3107.7 3218.6,3100.8 3217.4,3094 3215.4,3087.5 3212.7,3081.1 3209.3,3075.2 3205.2,3069.7 3200.5,3064.7 3195.2,3060.3 3189.5,3056.5 3183.3,3053.4 3176.9,3051.1 3170.2,3049.5 3163.4,3048.7 3156.5,3048.7 3149.7,3049.5 3143,3051.1 3136.6,3053.4 3130.4,3056.5 3124.7,3060.3 3119.4,3064.7 3114.7,3069.7 3110.6,3075.2 3107.2,3081.1 3104.4,3087.5 3102.5,3094 3101.3,3100.8 3100.9,3107.7 3101.3,3114.5 3102.5,3121.3 3104.4,3127.9 3107.2,3134.2 3110.6,3140.1 3114.7,3145.6 3119.4,3150.6 3124.7,3155 3130.4,3158.8 3136.6,3161.9 3143,3164.2 3149.7,3165.8 3156.5,3166.6 3163.4,3166.6 3170.2,3165.8 3176.9,3164.2 3183.3,3161.9 3189.5,3158.8 3195.2,3155 3200.5,3150.6 3205.2,3145.6 3209.3,3140.1 3212.7,3134.2 3215.4,3127.9 3217.4,3121.3 3218.6,3114.5
  lines w0.1: 3100.9,3107.7 3101.3,3100.8 3102.5,3094 3104.4,3087.5 3107.2,3081.1 3110.6,3075.2 3114.7,3069.7 3119.4,3064.7 3124.7,3060.3 3130.4,3056.5 3136.6,3053.4 3143,3051.1 3149.7,3049.5 3156.5,3048.7 3163.4,3048.7 3170.2,3049.5 3176.9,3051.1 3183.3,3053.4 3189.5,3056.5 3195.2,3060.3 3200.5,3064.7 3205.2,3069.7 3209.3,3075.2 3212.7,3081.1 3215.4,3087.5 3217.4,3094 3218.6,3100.8 3219,3107.7 3218.6,3114.5 3217.4,3121.3 3215.4,3127.9 3212.7,3134.2 3209.3,3140.1 3205.2,3145.6 3200.5,3150.6 3195.2,3155 3189.5,3158.8 3183.3,3161.9 3176.9,3164.2 3170.2,3165.8 3163.4,3166.6 3156.5,3166.6 3149.7,3165.8 3143,3164.2 3136.6,3161.9 3130.4,3158.8 3124.7,3155 3119.4,3150.6 3114.7,3145.6 3110.6,3140.1 3107.2,3134.2 3104.4,3127.9 3102.5,3121.3 3101.3,3114.5 3100.9,3107.7 ; 3100.9,7241.5 3101.3,7234.7 3102.5,7227.9 3104.4,7221.3 3107.2,7215 3110.6,7209.1 3114.7,7203.6 3119.4,7198.6 3124.7,7194.1 3130.4,7190.4 3136.6,7187.3 3143,7184.9 3149.7,7183.4 3156.5,7182.6 3163.4,7182.6 3170.2,7183.4 3176.9,7184.9 3183.3,7187.3 3189.5,7190.4 3195.2,7194.1 3200.5,7198.6 3205.2,7203.6 3209.3,7209.1 3212.7,7215 3215.4,7221.3 3217.4,7227.9 3218.6,7234.7 3219,7241.5 3218.6,7248.4 3217.4,7255.1 3215.4,7261.7 3212.7,7268 3209.3,7274 3205.2,7279.5 3200.5,7284.5 3195.2,7288.9 3189.5,7292.7 3183.3,7295.7 3176.9,7298.1 3170.2,7299.7 3163.4,7300.5 3156.5,7300.5 3149.7,7299.7 3143,7298.1 3136.6,7295.7 3130.4,7292.7 3124.7,7288.9 3119.4,7284.5 3114.7,7279.5 3110.6,7274 3107.2,7268 3104.4,7261.7 3102.5,7255.1 3101.3,7248.4 3100.9,7241.5 ; 4027.7,7255 4028.1,7248.2 4029.3,7241.5 4031.3,7234.9 4034,7228.7 4037.4,7222.8 4041.5,7217.3 4046.1,7212.3 4051.4,7208 4057.1,7204.2 4063.2,7201.1 4069.6,7198.8 4076.2,7197.2 4083,7196.4 4089.8,7196.4 4096.6,7197.2 4103.2,7198.8 4109.6,7201.1 4115.7,7204.2 4121.4,7208 4126.7,7212.3 4131.3,7217.3 4135.4,7222.8 4138.8,7228.7 4141.5,7234.9 4143.5,7241.5 4144.7,7248.2 4145.1,7255 4144.7,7261.8 4143.5,7268.5 4141.5,7275.1 4138.8,7281.3 4135.4,7287.3 4131.3,7292.7 4126.7,7297.7 4121.4,7302.1 4115.7,7305.8 4109.6,7308.9 4103.2,7311.2 4096.6,7312.8 4089.8,7313.6 4083,7313.6 4076.2,7312.8 4069.6,7311.2 4063.2,7308.9 4057.1,7305.8 4051.4,7302.1 4046.1,7297.7 4041.5,7292.7 4037.4,7287.3 4034,7281.3 4031.3,7275.1 4029.3,7268.5 4028.1,7261.8 4027.7,7255 ; 4656.8,7251.6 4657.6,7244.9 4659.1,7238.2 4661.4,7231.8 4664.4,7225.7 4668.1,7220 4672.4,7214.7 4677.3,7210 4682.7,7205.8 4688.5,7202.3 4694.7,7199.5 4701.2,7197.4 4707.8,7196 4714.6,7195.4 4721.4,7195.6 4728.2,7196.6 4734.7,7198.3 4741.1,7200.8 4747.1,7204 4752.7,7207.8 4757.9,7212.3 4762.5,7217.3 4766.5,7222.8 4769.8,7228.7 4772.5,7235 4774.4,7241.5 4775.5,7248.2 4775.9,7255 4775.5,7261.8 4774.4,7268.5 4772.5,7275 4769.8,7281.3 4766.5,7287.2 4762.5,7292.7 4757.9,7297.8 4752.7,7302.2 4747.1,7306.1 4741.1,7309.2 4734.7,7311.7 4728.2,7313.4 4721.4,7314.4 4714.6,7314.6 4707.8,7314 4701.2,7312.7 4694.7,7310.6 4688.5,7307.7 4682.7,7304.2 4677.3,7300.1 4672.4,7295.3 4668.1,7290 4664.4,7284.3 4661.4,7278.2 4659.1,7271.8 4657.6,7265.2 4656.8,7258.4 4656.8,7251.6 ; 6132.4,3107.7 6132.8,3100.8 6134,3094 6135.9,3087.5 6138.7,3081.1 6142.1,3075.2 6146.2,3069.7 6150.9,3064.7 6156.2,3060.3 6161.9,3056.5 6168,3053.4 6174.5,3051.1 6181.2,3049.5 6188,3048.7 6194.9,3048.7 6201.7,3049.5 6208.4,3051.1 6214.8,3053.4 6221,3056.5 6226.7,3060.3 6232,3064.7 6236.7,3069.7 6240.8,3075.2 6244.2,3081.1 6246.9,3087.5 6248.9,3094 6250.1,3100.8 6250.5,3107.7 6250.1,3114.5 6248.9,3121.3 6246.9,3127.9 6244.2,3134.2 6240.8,3140.1 6236.7,3145.6 6232,3150.6 6226.7,3155 6221,3158.8 6214.8,3161.9 6208.4,3164.2 6201.7,3165.8 6194.9,3166.6 6188,3166.6 6181.2,3165.8 6174.5,3164.2 6168,3161.9 6161.9,3158.8 6156.2,3155 6150.9,3150.6 6146.2,3145.6 6142.1,3140.1 6138.7,3134.2 6135.9,3127.9 6134,3121.3 6132.8,3114.5 6132.4,3107.7 ; 6132.4,7202.1 6132.8,7195.3 6134,7188.5 6135.9,7181.9 6138.7,7175.6 6142.1,7169.7 6146.2,7164.2 6150.9,7159.2 6156.2,7154.8 6161.9,7151 6168,7147.9 6174.5,7145.6 6181.2,7144 6188,7143.2 6194.9,7143.2 6201.7,7144 6208.4,7145.6 6214.8,7147.9 6221,7151 6226.7,7154.8 6232,7159.2 6236.7,7164.2 6240.8,7169.7 6244.2,7175.6 6246.9,7181.9 6248.9,7188.5 6250.1,7195.3 6250.5,7202.1 6250.1,7209 6248.9,7215.8 6246.9,7222.3 6244.2,7228.6 6240.8,7234.6 6236.7,7240.1 6232,7245.1 6226.7,7249.5 6221,7253.3 6214.8,7256.4 6208.4,7258.7 6201.7,7260.3 6194.9,7261.1 6188,7261.1 6181.2,7260.3 6174.5,7258.7 6168,7256.4 6161.9,7253.3 6156.2,7249.5 6150.9,7245.1 6146.2,7240.1 6142.1,7234.6 6138.7,7228.6 6135.9,7222.3 6134,7215.8 6132.8,7209 6132.4,7202.1
  lines w10: 3011.8,3010 3011.8,7375.1 6432.3,7375.1 6432.3,3010 3011.8,3010

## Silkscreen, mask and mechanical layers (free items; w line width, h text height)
Top Silkscreen Layer:
  drawing of 69 lines, arcs and shapes, not listed
  text "Main ESP" at 5226.8,6930 h120
  text "D+" at 4559.3,6775.2 h50 r90
  text "D-" at 4454.3,6760.7 h50 r90
  text "GND" at 4254.3,6739.6 h50 r90
  text "CC1" at 4354.3,6732.1 h50 r90
  text "CC2" at 4654.3,6725.6 h50 r90
  text "ET Type K" at 3351.8,6305 h80
  text "BT Type K" at 3371.8,5445 h80
  text "Crack ESP" at 4976.8,4000 h120
Mechanical Layer:
  drawing of 325 lines, arcs and shapes, not listed
Mech36:
  region: 6112.5,4310 6112.1,4306 6110.9,4302.1 6109,4298.5 6106.4,4295.4 6103.3,4292.8 6099.7,4290.9 6095.9,4289.7 6091.8,4289.3 6087.8,4289.7 6083.9,4290.9 6080.3,4292.8 6077.2,4295.4 6074.6,4298.5 6072.7,4302.1 6071.6,4306 6071.2,4310 6071.6,4314 6072.7,4317.9 6074.6,4321.5 6077.2,4324.6 6080.3,4327.2 6083.9,4329.1 6087.8,4330.3 6091.8,4330.7 6095.9,4330.3 6099.7,4329.1 6103.3,4327.2 6106.4,4324.6 6109,4321.5 6110.9,4317.9 6112.1,4314
  region: 3187.5,4625 3187.1,4621 3185.9,4617.1 3184,4613.5 3181.4,4610.4 3178.3,4607.8 3174.7,4605.9 3170.9,4604.7 3166.8,4604.3 3162.8,4604.7 3158.9,4605.9 3155.3,4607.8 3152.2,4610.4 3149.6,4613.5 3147.7,4617.1 3146.6,4621 3146.2,4625 3146.6,4629 3147.7,4632.9 3149.6,4636.5 3152.2,4639.6 3155.3,4642.2 3158.9,4644.1 3162.8,4645.3 3166.8,4645.7 3170.9,4645.3 3174.7,4644.1 3178.3,4642.2 3181.4,4639.6 3184,4636.5 3185.9,4632.9 3187.1,4629
  region: 3162.5,7260 3162.1,7256 3160.9,7252.1 3159,7248.5 3156.4,7245.4 3153.3,7242.8 3149.7,7240.9 3145.9,7239.7 3141.8,7239.3 3137.8,7239.7 3133.9,7240.9 3130.3,7242.8 3127.2,7245.4 3124.6,7248.5 3122.7,7252.1 3121.6,7256 3121.2,7260 3121.6,7264 3122.7,7267.9 3124.6,7271.5 3127.2,7274.6 3130.3,7277.2 3133.9,7279.1 3137.8,7280.3 3141.8,7280.7 3145.9,7280.3 3149.7,7279.1 3153.3,7277.2 3156.4,7274.6 3159,7271.5 3160.9,7267.9 3162.1,7264
  region: 6112.5,7260 6112.1,7256 6110.9,7252.1 6109,7248.5 6106.4,7245.4 6103.3,7242.8 6099.7,7240.9 6095.9,7239.7 6091.8,7239.3 6087.8,7239.7 6083.9,7240.9 6080.3,7242.8 6077.2,7245.4 6074.6,7248.5 6072.7,7252.1 6071.6,7256 6071.2,7260 6071.6,7264 6072.7,7267.9 6074.6,7271.5 6077.2,7274.6 6080.3,7277.2 6083.9,7279.1 6087.8,7280.3 6091.8,7280.7 6095.9,7280.3 6099.7,7279.1 6103.3,7277.2 6106.4,7274.6 6109,7271.5 6110.9,7267.9 6112.1,7264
